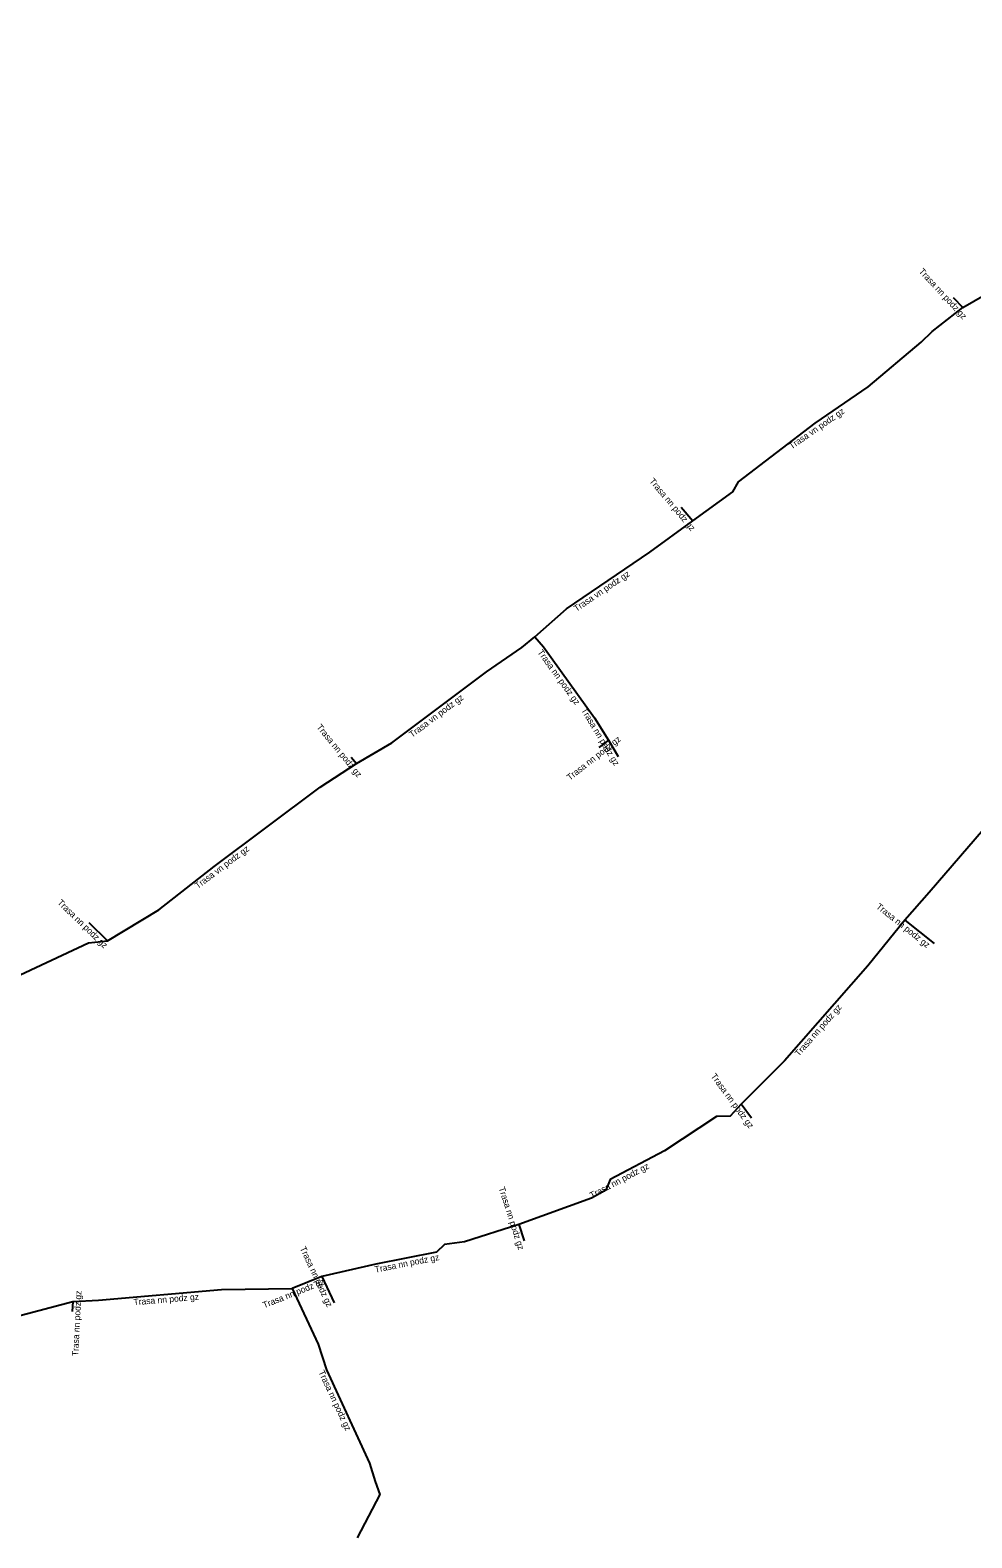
# Model space of a CAD drawing. Extents: x -688315 to -687940, y -1059595 to -1059240.
# Drawn here: x -688130 to -688055.8, y -1059484.8 to -1059366 of the extents above; entities that cross this region are included whole.
import ezdxf

# ---------------------------------------------------------------- set-up
doc = ezdxf.new("R2010")
doc.units = 0
for name, color, linetype in [('Popiskový text - Ostatní atributy Trasy', 7, 'Continuous'), ('Spojnice NN', 7, 'Continuous'), ('Spojnice VN', 7, 'Continuous')]:
    doc.layers.add(name, color=color, linetype=linetype)

msp = doc.modelspace()

# ---------------------------------------------------------------- linework, layer by layer
at = {"layer": 'Spojnice NN'}
for points in [[(-688057.25, -1059387.07), (-688056.51, -1059387.87)], [(-688078.68, -1059403.58), (-688077.77, -1059404.66)], [(-688090.2, -1059413.79), (-688089.54, -1059414.59), (-688085.51, -1059420.18), (-688084.42, -1059421.93)], [(-688045.56, -1059419.48), (-688053.26, -1059428.7), (-688054.87, -1059428.98), (-688059.16, -1059433.94), (-688061.07, -1059436.12)], [(-688084.42, -1059421.93), (-688085.17, -1059422.52)], [(-688084.42, -1059421.93), (-688083.64, -1059423.23)], [(-688104.67, -1059423.28), (-688104.26, -1059423.78)], [(-688061.07, -1059436.12), (-688063.99, -1059439.72), (-688070.54, -1059447.18), (-688073.95, -1059450.61)], [(-688061.07, -1059436.12), (-688058.75, -1059437.96)], [(-688125.35, -1059436.3), (-688123.87, -1059437.73)], [(-688073.95, -1059450.61), (-688074.82, -1059451.54), (-688075.91, -1059451.57), (-688079.99, -1059454.28), (-688084.27, -1059456.55), (-688084.62, -1059457.39), (-688085.76, -1059458.02), (-688091.47, -1059460.08)], [(-688073.14, -1059451.71), (-688073.95, -1059450.61)], [(-688091.47, -1059460.08), (-688095.76, -1059461.44), (-688097.33, -1059461.66), (-688097.95, -1059462.26), (-688102.74, -1059463.21), (-688106.99, -1059464.17)], [(-688091.47, -1059460.08), (-688091.06, -1059461.36)], [(-688106.99, -1059464.17), (-688109.33, -1059465.11)], [(-688106.99, -1059464.17), (-688106.03, -1059466.25)], [(-688126.61, -1059466.14), (-688124.58, -1059466.04), (-688114.89, -1059465.2), (-688109.33, -1059465.11)], [(-688109.33, -1059465.11), (-688107.29, -1059469.5), (-688106.63, -1059471.53), (-688103.23, -1059478.87), (-688102.78, -1059480.31), (-688102.43, -1059481.35), (-688104.2, -1059484.76)], [(-688142.88, -1059470.78), (-688137.54, -1059469.47), (-688135.05, -1059468.38), (-688126.61, -1059466.14)], [(-688126.61, -1059466.14), (-688126.65, -1059466.93)]]:
    msp.add_lwpolyline(points, dxfattribs=at)
at = {"layer": 'Spojnice VN'}
for points in [[(-688056.51, -1059387.87), (-688054.76, -1059386.87), (-688053.54, -1059387.22), (-688050.29, -1059388.27), (-688040.59, -1059384.22), (-688035.35, -1059380.43), (-688029.78, -1059377.14), (-688026.06, -1059374.33), (-688021.86, -1059370.77), (-688016.26, -1059366.02)], [(-688077.77, -1059404.66), (-688074.62, -1059402.37), (-688074.17, -1059401.59), (-688068.13, -1059396.98), (-688063.96, -1059394.1), (-688059.79, -1059390.59), (-688058.92, -1059389.76), (-688056.51, -1059387.87)], [(-688090.2, -1059413.79), (-688087.73, -1059411.6), (-688081.15, -1059407.14), (-688077.77, -1059404.66)], [(-688104.26, -1059423.78), (-688101.47, -1059422.14), (-688094.02, -1059416.55), (-688091.23, -1059414.63), (-688090.2, -1059413.79)], [(-688123.87, -1059437.73), (-688119.84, -1059435.31), (-688115.47, -1059431.89), (-688107.13, -1059425.63), (-688104.26, -1059423.78)], [(-688143.47, -1059445.15), (-688138.64, -1059443.91), (-688131.6, -1059440.82), (-688125.38, -1059437.89), (-688123.87, -1059437.73)]]:
    msp.add_lwpolyline(points, dxfattribs=at)

# ---------------------------------------------------------------- texts
at = {"layer": 'Popiskový text - Ostatní atributy Trasy'}
for s, rotation, p in [('Trasa nn podz gz', 312.7688, (-688060, -1059385.05)), ('Trasa vn podz gz', 34.6308, (-688069.98, -1059399.05)), ('Trasa nn podz gz', 310.1172, (-688081.23, -1059401.56)), ('Trasa vn podz gz', 34.1299, (-688086.93, -1059411.84)), ('Trasa nn podz gz', 305.789, (-688090.03, -1059415.02)), ('Trasa vn podz gz', 36.8822, (-688099.88, -1059421.76)), ('Trasa nn podz gz', 300.9638, (-688086.59, -1059419.58)), ('Trasa nn podz gz', 309.3518, (-688107.44, -1059420.93)), ('Trasa nn podz gz', 38.1909, (-688087.45, -1059425.14)), ('Trasa vn podz gz', 36.8919, (-688116.76, -1059433.67)), ('Trasa nn podz gz', 315.9844, (-688127.86, -1059434.78)), ('Trasa nn podz gz', 321.5819, (-688063.37, -1059435.13)), ('Trasa nn podz gz', 48.7163, (-688069.41, -1059446.88)), ('Trasa nn podz gz', 306.3666, (-688076.38, -1059448.41)), ('Trasa nn podz gz', 27.9403, (-688085.72, -1059458.05)), ('Trasa nn podz gz', 287.7609, (-688093.07, -1059457.21)), ('Trasa nn podz gz', 294.7751, (-688108.73, -1059461.95)), ('Trasa nn podz gz', 11.2179, (-688102.77, -1059463.88)), ('Trasa nn podz gz', 21.8858, (-688111.53, -1059466.69)), ('Trasa nn podz gz', 87.1014, (-688126.18, -1059470.46)), ('Trasa nn podz gz', 4.9544, (-688121.8, -1059466.45)), ('Trasa nn podz gz', 294.8543, (-688107.27, -1059471.7))]:
    msp.add_text(s, height=0.5, rotation=rotation, dxfattribs=at).set_placement(p)

doc.saveas('drawing.dxf')
